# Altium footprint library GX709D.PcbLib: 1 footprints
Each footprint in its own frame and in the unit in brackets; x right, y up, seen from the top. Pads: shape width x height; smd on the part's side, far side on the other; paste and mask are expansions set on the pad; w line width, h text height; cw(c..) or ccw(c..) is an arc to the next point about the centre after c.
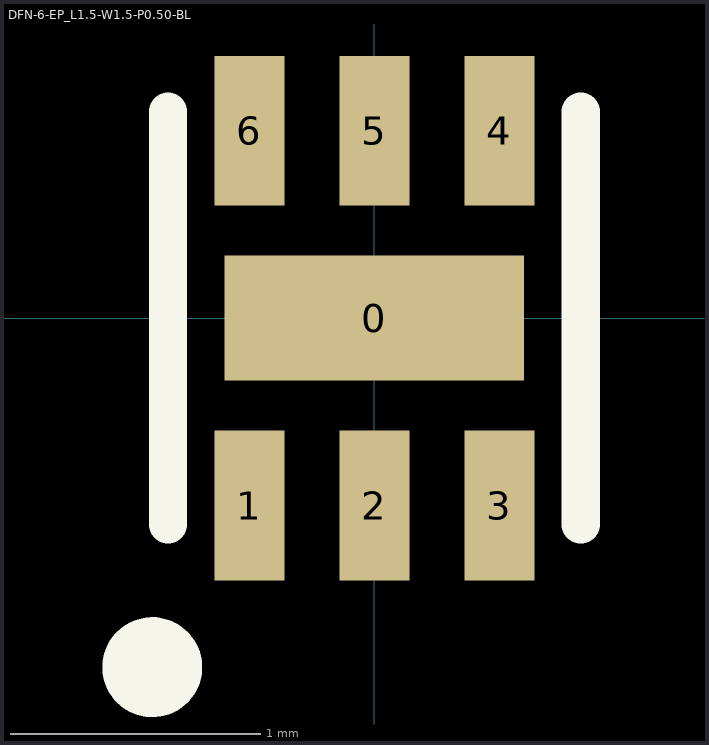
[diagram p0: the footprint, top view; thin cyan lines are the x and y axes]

## DFN-6-EP_L1.5-W1.5-P0.50-BL [mm]
pads (7):
  rect 1.2x0.5 smd: 0(0,0)
  rect 0.28x0.6 smd: 1(-0.5,-0.75) 2(0,-0.75) 3(0.5,-0.75) 4(0.5,0.75) 5(0,0.75) 6(-0.5,0.75)
Top Overlay:
  circle w0.2: c-0.889,-1.397 r0.1
  lines w0.152: -0.826,-0.826 -0.826,0.826 ; 0.826,-0.826 0.826,0.826
3D body "DFN-6L-1.5X1.5-P0.5.STEP": height 0.52, standoff 0, extent -0.738,-0.77 0.762,0.77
